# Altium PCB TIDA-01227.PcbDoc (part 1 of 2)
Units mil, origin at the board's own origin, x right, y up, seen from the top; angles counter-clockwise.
Board outline 2300 x 2250 mil, 2 copper layers (Top Layer, Bottom Layer), stack 64.8 mil thick; 107 components, 78 nets, 446 pads, 341 vias.
Unrouted connection lines stored in the file: 1.
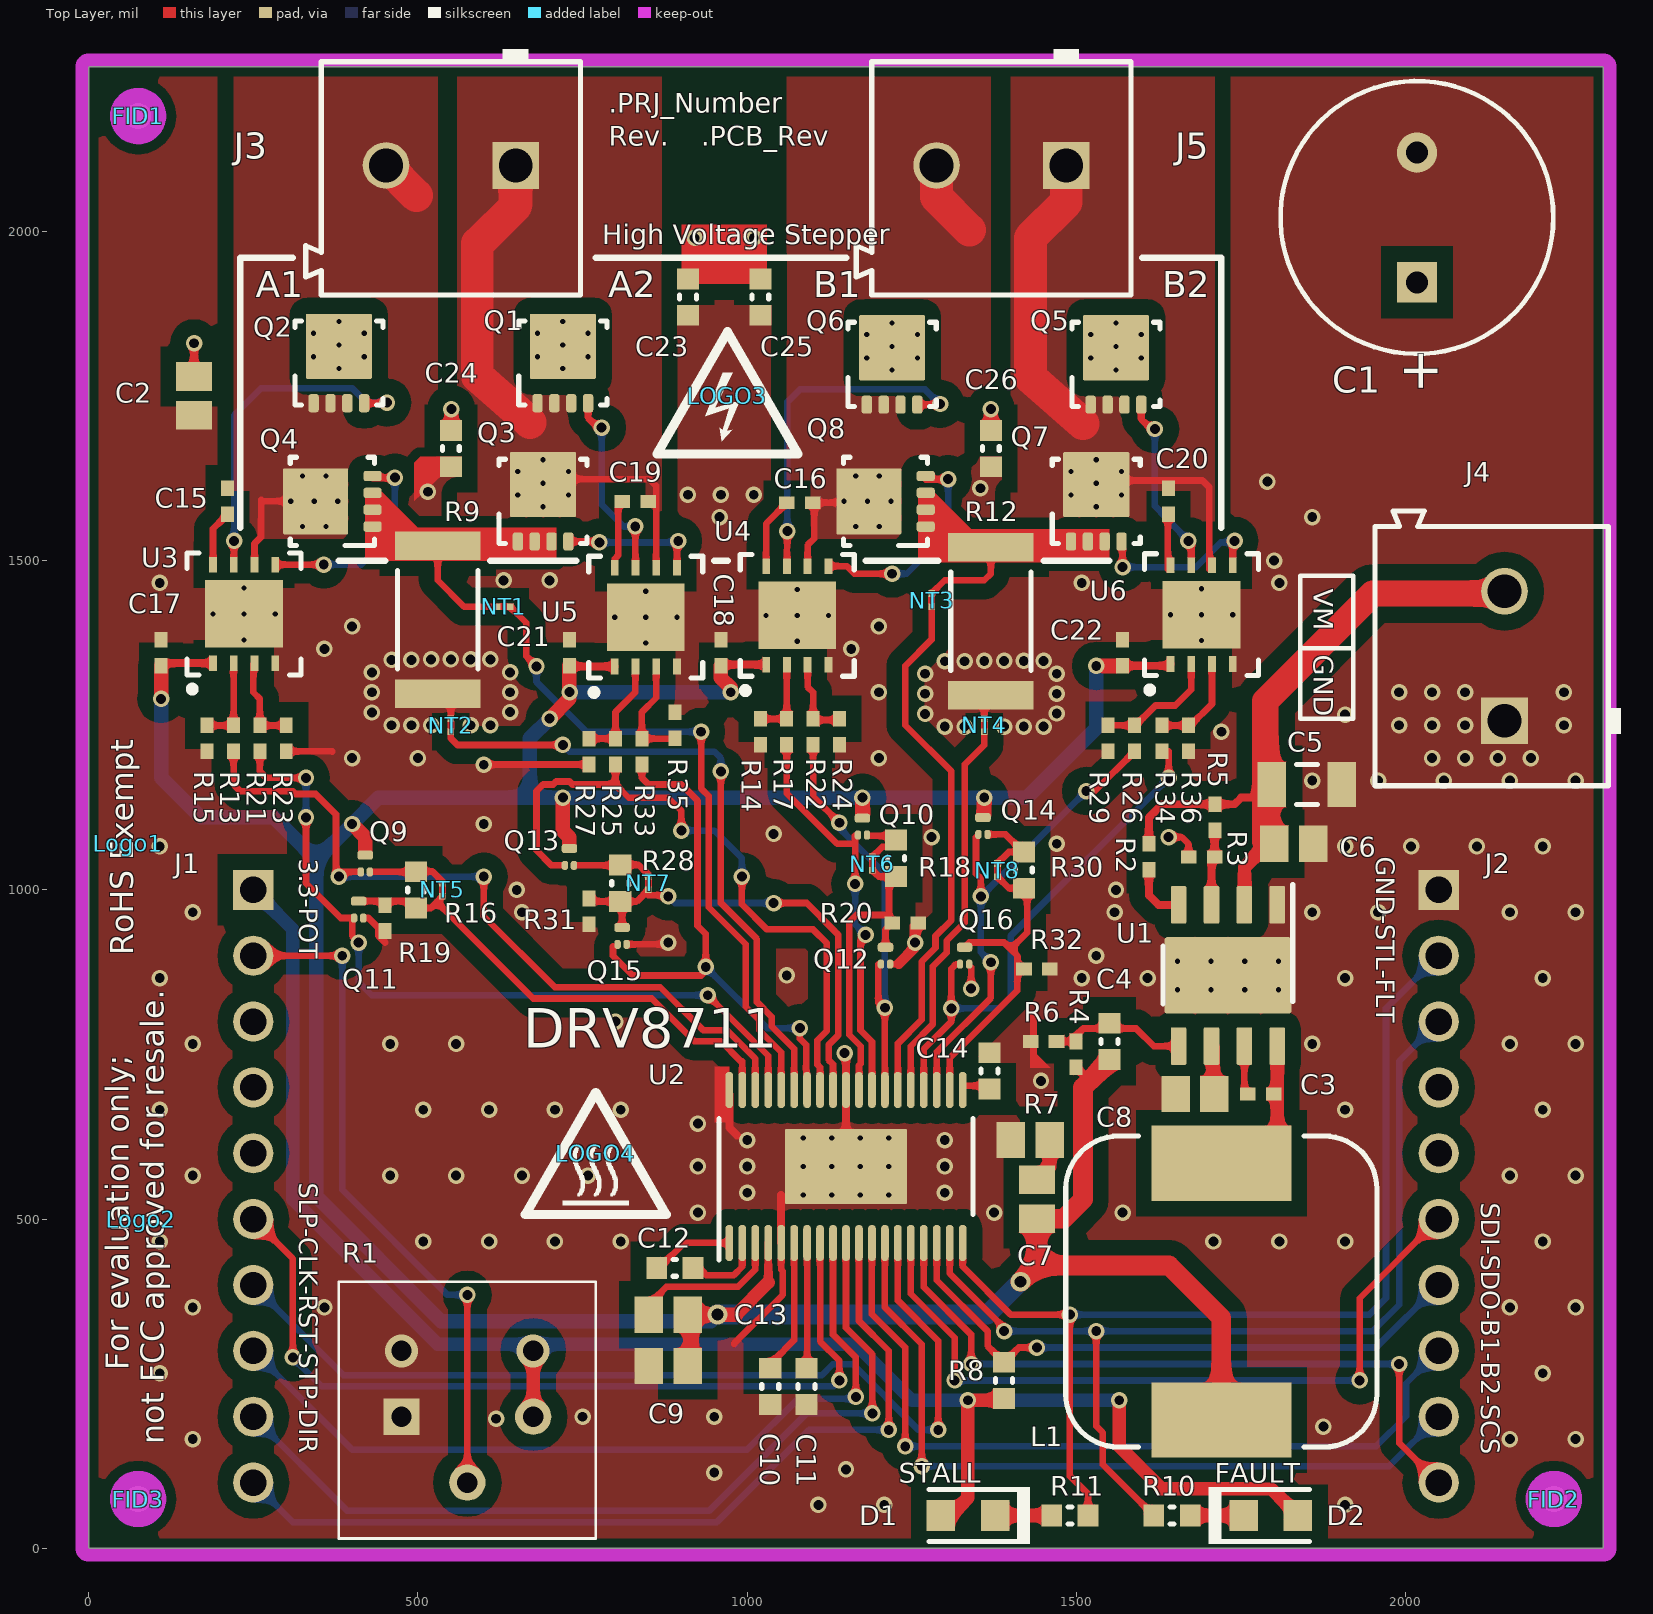
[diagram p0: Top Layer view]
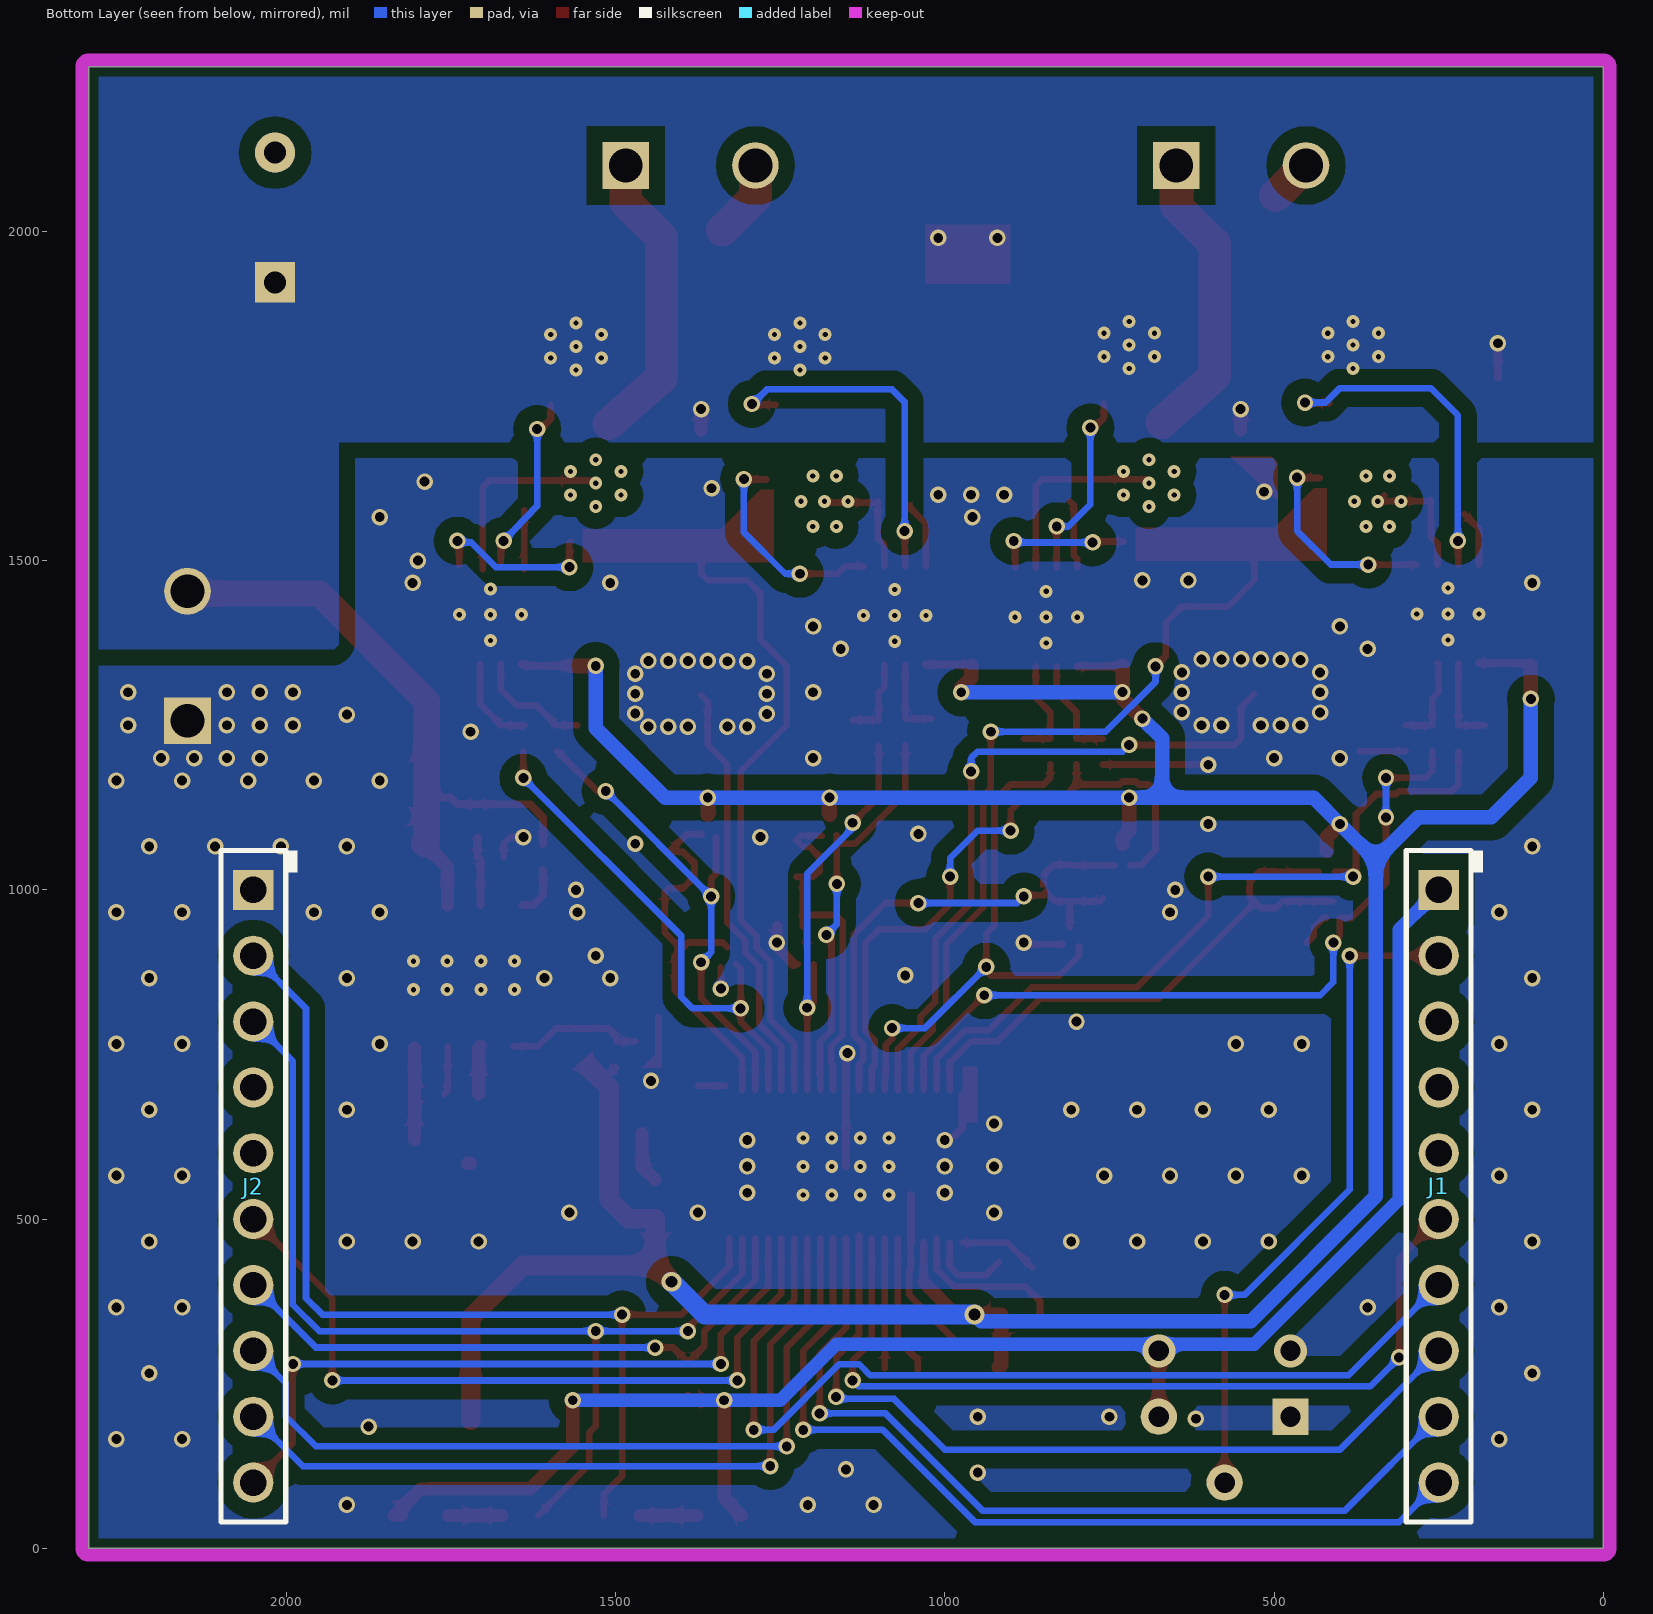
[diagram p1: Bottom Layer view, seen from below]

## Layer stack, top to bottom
Top Solder: solder mask 0.4, Solder Resist, Dk 3.5
Top Layer: signal copper 2.8
Dielectric1: core 59.2, FR-4, Dk 4.8
Bottom Layer: signal copper 2.8
Bottom Solder: solder mask 0.4, Solder Resist, Dk 3.5

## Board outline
0,0 0,2250 2300,2250 2300,0

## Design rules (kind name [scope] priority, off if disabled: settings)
AcuteAngle [All] p1: minimum=4.50000000000000E+0001 checktracksonly=FALSE
AssemblyTestPointUsage [All] p1: valid=2
Clearance Clearance_BoardEdge_MountingHoles [OnCopper and InComponentClass('Mounting Holes') vs IsKeepOut] p1: gap=15
Clearance Clearance_BoardEdge_Poly [OnCopper and InPoly vs IsKeepOut] p2: gap=15
Clearance Clearance_BoardEdge [OnCopper and Not InComponentClass('Logo') and not InComponentClass('FiducialMark') and not InRegion(1000,500,4000,800) and Not IsKeepout vs IsKeepOut] p3: gap=25
Clearance Clearance_Poly [InPolygon] p4: gap=14 except(24: Arc-Poly Track-Poly SMDPad-Poly THPad-Poly Via-Poly Fill-Poly Poly-Poly)
Clearance [All] p5: gap=7 except(3.94: SMDPad-SMDPad)
ComponentClearance ComponentClearance_Logo [InComponentClass(Logo)] p1: gap=10 collisioncheckmode=3 verticalgap=10 showdistances=FALSE
ComponentClearance ComponentClearance_ScrewToNut [(HasFootprint('NY PMS 440 0025 PH')) vs (HasFootprint('Keystone_1902C'))] p2: gap=5 collisioncheckmode=3 verticalgap=10 showdistances=FALSE
ComponentClearance ComponentClearance_MountingHoles [InComponentClass('Mounting Holes')] p3: gap=250 collisioncheckmode=3 verticalgap=100000 showdistances=FALSE
ComponentClearance ComponentClearance_SmallPassives [HasFootprint('0201*') or HasFootprint('0402*') or HasFootprint('0508') or HasFootprint('0603*') or HasFootprint('0612') or HasFootprint('0805*') or HasFootprint('0815*') or HasFootprint('0830*') or HasFootprint('1206*') or HasFootprint('1210*') or HasFootprint('1808*') or HasFootprint('1812*') or HasFootprint('1825*') or HasFootprint('2010*') or HasFootprint('2220*') or HasFootprint('2225*') or HasFootprint('2512*') or HasFootprint('2728*') or HasFootprint('3518*') vs HasFootprint('0201*') or HasFootprint('0402*') or HasFootprint('0508') or HasFootprint('0603*') or HasFootprint('0612') or HasFootprint('0805*') or HasFootprint('0815*') or HasFootprint('0830*') or HasFootprint('1206*') or HasFootprint('1210*') or HasFootprint('1808*') or HasFootprint('1812*') or HasFootprint('1825*') or HasFootprint('2010*') or HasFootprint('2220*') or HasFootprint('2225*') or HasFootprint('2512*') or HasFootprint('2728*') or HasFootprint('3518*')] p4: gap=10 collisioncheckmode=3 verticalgap=10 showdistances=FALSE
ComponentClearance ComponentClearance_THtoSMT [IsThruComponent vs IsSMTComponent] p5: gap=10 collisioncheckmode=3 verticalgap=100000 showdistances=FALSE
ComponentClearance ComponentClearance_THtoTH [IsThruComponent vs IsThruComponent] p6: gap=0 collisioncheckmode=3 verticalgap=0 showdistances=FALSE
ComponentClearance [All] p7: gap=10 collisioncheckmode=3 verticalgap=10 showdistances=FALSE
DiffPairsRouting [All] p1: maxlimit=100 minlimit=10 mostfreqgap=10 toplayer_minwidth=15 toplayer_maxwidth=15 toplayer_prefwidth=15 bottomlayer_minwidth=15 bottomlayer_maxwidth=15 bottomlayer_prefwidth=15 maxuncoupledlength=1000
FabricationTestPointUsage TestPointUsage [All] p1: valid=2 allowmultiple=FALSE
FabricationTestpoint Testpoint [All] p1: side=3 testpointundercomponent=TRUE minsize=40 maxsize=100 preferedsize=60 minholesize=0 maxholesize=40 preferedholesize=32 testpointgrid=1 allowsidetop=TRUE allowsidebottom=TRUE usegrid=TRUE gridtolerance=0.01
FanoutControl Fanout_LCC [IsLCC] p1: bgadir=Out bgaviamode=Centered fanoutstyle=Auto fanoutdirection=Alternating viagrid=1 // Fanout_LCC (Default Rule)
FanoutControl Fanout_BGA [IsBGA] p2: bgadir=Out bgaviamode=Centered fanoutstyle=Auto fanoutdirection=Alternating viagrid=1 // Fanout_BGA (Default Rule)
FanoutControl Fanout_Default [All] p4: bgadir=Out bgaviamode=Centered fanoutstyle=Auto fanoutdirection=Alternating viagrid=1 // Fanout_Default (Default Rule)
FanoutControl Fanout_Small [(CompPinCount < 5)] p5: bgadir=Out bgaviamode=Centered fanoutstyle=Auto fanoutdirection=OutThenIn viagrid=1 // Fanout_Small (Default Rule)
HoleSize [All] p1: absolutevalues=TRUE maxlimit=251 minlimit=7.8 maxpercent=80.000 minpercent=20.000
MinimumAnnularRing [All] p1: minimumring=5
MinimumSolderMaskSliver MinimumSolderMaskSliver_Logo [InComponentClass('Logo') vs InComponentClass('Logo')] p1: minsoldermaskwidth=0.7
MinimumSolderMaskSliver [All] p2: minsoldermaskwidth=0.4
PlaneClearance [All] p1: clearance=15
PlaneConnect [All] p1: planeconnectstyle=Direct reliefexpansion=10 reliefentries=4 reliefconductorwidth=10 reliefairgap=10
PolygonConnect PolygonConnect_1 [IsNamedPolygon('GND_TOP') or IsNamedPolygon('GND_BOT') vs Not (InComponent('U1') or InComponent('J2') or InComponent('J3') or InComponent('J5') or InComponent('C1') or InComponent('R1') or InComponent('R2') or IsStitchingVia or IsVia)] p1: connectstyle=Direct reliefconductorwidth=10 reliefentries=4 polygonreliefangle="90 Angle" airgapwidth=10
PolygonConnect [All] p2: connectstyle=Direct reliefconductorwidth=10 reliefentries=4 polygonreliefangle="90 Angle" airgapwidth=10
RoutingVias [All] p1: holewidth=15 width=25 viastyle="Through Hole" minholewidth=7.8 minwidth=19 maxholewidth=40 maxwidth=65
SMDToCorner [All] p1: distance=15000
SilkToSilkClearance [All] p1: silktosilkclearance=2
SilkToSolderMaskClearance SilkscreenOverComponentPads [All] p1: minsilkscreentomaskgap=1 clearancetoexposedcopper=FALSE
SolderMaskExpansion [All] p1: expansion=3
Width [All] p1: maxlimit=100 minlimit=6 preferedwidth=10 checkconnectedcopper=TRUE
15 further rules are at their usual default settings.

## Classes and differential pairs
component class FiducialMark: FID1 FID2 FID3
component class TIDA-01227_Driver_and_FETs: C9 C10 C11 C12 C13 C14 C23 C24 C25 C26 D1 D2 NT1 NT2 NT3 NT4 Q1 Q2 Q3 Q4 Q5 Q6 Q7 Q8 R8 R9 R10 R11 R12 U2
component class TIDA-01227_Connectors_and_Buck: C1 C2 C3 C4 C5 C6 C7 C8 FID1 FID2 FID3 J1 J2 J3 J4 J5 L1 Logo1 Logo2 LOGO4 R1 R2 R3 R4 R5 R6 R7 U1
component class TIDA-01227_HV_translation: C15 C16 C17 C18 C19 C20 C21 C22 NT5 NT6 NT7 NT8 Q9 Q10 Q11 Q12 Q13 Q14 Q15 Q16 R13 R14 R15 R16 R17 R18 R19 R20 R21 R22 R23 R24 R25 R26 R27 R28 R29 R30 R31 R32 R33 R34 R35 R36 U3 U4 U5 U6

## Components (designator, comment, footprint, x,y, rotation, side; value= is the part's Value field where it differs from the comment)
C1 "ECA-2AHG101" NHG_1000x2000 2017,2021 r90 top
C2 "C0805C104K1RACTU" 0805L 160,1750 r270 top
C3 "885012205031" 0402L 1780,690 r0 top
C4 "06031C562JAT2A" 0603L 1550,770 r90 top
C5 "C3216X7R2A105M160AA" 1206L 1850,1160 r0 top
C6 "C2012X7R2A104K125AA" 0805L 1830,1070 r0 top
C7 "CL21A106KAFN3NE" 0805L 1440,530 r90 top
C8 "GRM21BR71H105KA12L" 0805L 1680,690 r180 top
C9 "GRM21BR71H105KA12L" 0805L 880,277 r180 top
C10 "GRM188R72A104KA35D" 0603L 1035,246 r270 top
C11 "GRM188R71E105KA12D" 0603L 1090,246 r270 top
C12 "GRM188R72A104KA35D" 0603L 890,426 r0 top
C13 "GRM21BR71H105KA12L" 0805L 880,355 r0 top
C14 "C0603X102K5RACTU" 0603L 1368,725 r90 top
C15 "C1005X7R1E104M050BB" 0402L 210.84,1590 r270 top
C16 "C1005X7R1E104M050BB" 0402L 1080,1587.8 r180 top
C17 "C1005X7R1E104M050BB" 0402L 110,1360 r90 top
C18 "C1005X7R1E104M050BB" 0402L 960,1360 r90 top
C19 "C1005X7R1E104M050BB" 0402L 830,1590 r180 top
C20 "C1005X7R1E104M050BB" 0402L 1640,1590 r270 top
C21 "C1005X7R1E104M050BB" 0402L 730,1360 r90 top
C22 "C1005X7R1E104M050BB" 0402L 1570,1360 r90 top
C23 "GRM188R72A104KA35D" 0603L 910,1900 r270 top
C24 "GRM188R72A104KA35D" 0603L 550,1670 r270 top
C25 "GRM188R72A104KA35D" 0603L 1020,1900 r270 top
C26 "GRM188R72A104KA35D" 0603L 1370,1670 r270 top
D1 "150080SS75000" WL-SMCW_RED_0805 1335,50 r180 top
D2 "150080SS75000" WL-SMCW_RED_0805 1795,50 r0 top
FID1 "Fiducial" Fiducial10-20 75,2175 r0 top
FID2 "Fiducial" Fiducial10-20 2225,75 r0 top
FID3 "Fiducial" Fiducial10-20 75,75 r0 top
J1 "61301011821" Wurth_61301011821 250,550 r270 bottom locked
J2 "61301011821" Wurth_61301011821 2050,550 r270 bottom
J3 "691 101 710 002" Wurth_691101710002 550,2100 r180 top
J4 "691 101 710 002" Wurth_691101710002 2150,1355 r90 top
J5 "691 101 710 002" Wurth_691101710002 1386,2100 r180 top
L1 "744770222" WE-PD_1280 1720,390 r270 top
Logo1 "EU RoHS Exempt Logo" EURoHS_Exempt_60mil 60,1070 r90 top
Logo2 "FCC disclaimer" FCC_disclaimer_stacked 80,500 r90 top
LOGO3 "DANGER HIGH VOLTAGE" IEC_HighVoltage_Small 970,1750 r0 top
LOGO4 "CAUTION HOT SURFACE" IEC_HotSurface_Small 770,600 r0 top
NT1 "Net-Tie" Net-Tie_10mil 630,1430 r180 top net-tie
NT2 "Net-Tie" Net-Tie_10mil 550,1250 r90 top net-tie
NT3 "Net-Tie" Net-Tie_10mil 1280,1440 r270 top net-tie
NT4 "Net-Tie" Net-Tie_10mil 1360,1250 r270 top net-tie
NT5 "Net-Tie" Net-Tie_10mil 537.2,1000 r90 top net-tie
NT6 "Net-Tie" Net-Tie_10mil 1190,1040 r90 top net-tie
NT7 "Net-Tie" Net-Tie_10mil 850,1010 r90 top net-tie
NT8 "Net-Tie" Net-Tie_10mil 1380,1030 r90 top net-tie
Q1 "CSD19538Q3A" DNH0008A 720,1800 r90 top
Q2 "CSD19538Q3A" DNH0008A 380,1800 r90 top
Q3 "CSD19538Q3A" DNH0008A 690,1590 r90 top
Q4 "CSD19538Q3A" DNH0008A 370,1590 r180 top
Q5 "CSD19538Q3A" DNH0008A 1560,1797.8 r90 top
Q6 "CSD19538Q3A" DNH0008A 1220,1797.8 r90 top
Q7 "CSD19538Q3A" DNH0008A 1530,1590 r90 top
Q8 "CSD19538Q3A" DNH0008A 1210,1590 r180 top
Q9 "CSD17483F4T" YJC0003A 420,1040 r90 top
Q10 "CSD17483F4T" YJC0003A 1175,1096 r90 top
Q11 "CSD17483F4T" YJC0003A 410,970 r90 top
Q12 "CSD17483F4T" YJC0003A 1210,900 r90 top
Q13 "CSD17483F4T" YJC0003A 730,1050 r90 top
Q14 "CSD17483F4T" YJC0003A 1358,1097 r90 top
Q15 "CSD17483F4T" YJC0003A 810,930 r90 top
Q16 "CSD17483F4T" YJC0003A 1330,900 r90 top
R1 "3386P-1-104LF" BOURNS_3386P 575,210 r0 top locked
R2 "CRCW0402267KFKED" 0402L 1610,1050 r270 top
R3 "CRCW040251K1FKED" 0402L 1710,1110 r90 top
R4 "CRCW04022K67FKED" 0402L 1499,750 r270 top
R5 "CRCW04029K09FKED" 0402L 1690,1050 r0 top
R6 "CRCW0402301RFKED" 0402L 1450,770 r0 top
R7 "ERJ-6RQF2R2V" 0805L 1430,620 r0 top
R8 "CRCW06033K30JNEA" 0603L 1390,255 r270 top
R9 "CRA2512-FZ-R050ELF" 2512L 530,1410 r90 top
R10 "CRCW0603330RJNEA" 0603L 1645,50 r180 top
R11 "CRCW0603330RJNEA" 0603L 1490,50 r180 top
R12 "CRA2512-FZ-R050ELF" 2512L 1370,1407.8 r90 top
R13 "CRCW040218K0FKED" 0402L 220,1230 r270 top
R14 "CRCW040218K0FKED" 0402L 1060,1240 r270 top
R15 "CRCW04023K01FKED" 0402L 180,1230 r90 top
R16 "CRCW0603100RJNEA" 0603L 497.2,1000 r90 top
R17 "CRCW04023K01FKED" 0402L 1020,1240 r90 top
R18 "CRCW0603100RJNEA" 0603L 1226,1048 r90 top
R19 "CRCW0402100KFKED" 0402L 450,957.2 r90 top
R20 "CRCW0402100KFKED" 0402L 1240,950 r180 top
R21 "CRCW040214K0FKED" 0402L 260,1230 r270 top
R22 "CRCW040214K0FKED" 0402L 1100,1240 r270 top
R23 "CRCW04026K98FKED" 0402L 300,1230 r90 top
R24 "CRCW04026K98FKED" 0402L 1140,1240 r90 top
R25 "CRCW040218K0FKED" 0402L 800,1210 r270 top
R26 "CRCW040218K0FKED" 0402L 1588.19,1230 r270 top
R27 "CRCW04023K01FKED" 0402L 760,1210 r90 top
R28 "CRCW0603100RJNEA" 0603L 807.2,1010 r90 top
R29 "CRCW04023K01FKED" 0402L 1548.19,1230 r90 top
R30 "CRCW0603100RJNEA" 0603L 1420,1030 r90 top
R31 "CRCW0402100KFKED" 0402L 760,967.2 r90 top
R32 "CRCW0402100KFKED" 0402L 1440,880 r180 top
R33 "CRCW040214K0FKED" 0402L 840,1210 r270 top
R34 "CRCW040214K0FKED" 0402L 1630,1230 r270 top
R35 "CRCW04026K98FKED" 0402L 890,1250 r270 top
R36 "CRCW04026K98FKED" 0402L 1670,1230 r90 top
U1 "LM5017MRX/NOPB" DDA0008B_N 1730,870 r270 top
U2 "DRV8711DCPR" DCP0038A_N 1150,580 r90 top
U3 "LM5107SD/NOPB" SDC08A 236,1419 r90 top
U4 "LM5107SD/NOPB" SDC08A 1076,1416.8 r90 top
U5 "LM5107SD/NOPB" SDC08A 846,1414 r90 top
U6 "LM5107SD/NOPB" SDC08A 1690,1417.8 r90 top

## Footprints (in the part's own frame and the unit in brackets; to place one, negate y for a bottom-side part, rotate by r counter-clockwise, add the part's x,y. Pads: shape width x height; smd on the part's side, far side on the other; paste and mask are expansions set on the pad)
0402L [mm] "0402 from SM-752 data"
  rect 0.6x0.5 smd: 1(-0.5,0) 2(0.5,0)
  body extent -0.55,-0.3 0.55,0.3, height 0.6
0603L [mm] "0603 from SM-752 data"
  rect 0.8x0.85 smd: 1(-0.7,0) 2(0.7,0)
  silkscreen extent -0.07,-0.33 0.07,0.33, body extent -0.87,-0.47 0.87,0.47, height 1
0805L [mm] "0805 from SM-752 data"
  rect 1.1x1.4 smd: 1(-0.75,0) 2(0.75,0)
  body extent -1.1,-0.72 1.1,0.72, height 1.45
1206L [mm] "1206 from SM-752 data"
  rect 1.1x1.75 smd: 1(-1.35,0) 2(1.35,0)
  silkscreen extent -0.4,-0.77 0.4,0.77, body extent -1.7,-0.9 1.7,0.9, height 1.35
2512L [mm] "Chip Resistor, Body 6.3x3.2mm, IPC High Density"
  rect 1.1x3.3 smd: 1(-2.85,0) 2(2.85,0)
  silkscreen extent -1.9,-1.55 1.9,1.55, body extent -3.22,-1.67 3.22,1.67, height 0.71
BOURNS_3386P [mil] "BOURND"
  rect 55x55 hole 31: 1(-100,-10)
  round 55 hole 31: 2(0,-110) 3(100,-10)
  silkscreen extent -195,-195 195,195, body extent -193,-192 193,193, height 201
DCP0038A_N [mm] "SOP, 38-Leads, Body 9.8x4.5mm, Pitch 0.5mm, Thermal Pad 4.7x2.9mm, IPC Medium Density"
  oval 1.4x0.3 smd: 1(-2.95,4.5) 2(-2.95,4) 3(-2.95,3.5) 4(-2.95,3) 5(-2.95,2.5) 6(-2.95,2) 7(-2.95,1.5) 8(-2.95,1) 9(-2.95,0.5) 10(-2.95,0) 11(-2.95,-0.5) 12(-2.95,-1) 13(-2.95,-1.5) 14(-2.95,-2) 15(-2.95,-2.5) 16(-2.95,-3) 17(-2.95,-3.5) 18(-2.95,-4) 19(-2.95,-4.5) 20(2.95,-4.5) 21(2.95,-4) 22(2.95,-3.5) 23(2.95,-3) 24(2.95,-2.5) 25(2.95,-2) 26(2.95,-1.5) 27(2.95,-1) 28(2.95,-0.5) 29(2.95,0) 30(2.95,0.5) 31(2.95,1) 32(2.95,1.5) 33(2.95,2) 34(2.95,2.5) 35(2.95,3) 36(2.95,3.5) 37(2.95,4) 38(2.95,4.5)
  rrect3% 2.9x4.7 smd: 39(0,0)
  silkscreen extent -3.6,-4.9 1.85,4.9, body extent -3.21,-4.85 3.21,4.85, height 1.2
DDA0008B_N [mm] "SOIC, 8-Leads, Body 4.9x3.9mm, Pitch 1.27mm, Exposed Pad, IPC Medium Density"
  rrect17% 1.45x0.6 smd: 1(-2.725,1.905) 2(-2.725,0.635) 3(-2.725,-0.635) 4(-2.725,-1.905) 5(2.725,-1.905) 6(2.725,-0.635) 7(2.725,0.635) 8(2.725,1.905)
  rrect7% 2.95x4.9 smd paste-1.5 mask-1.5: 9(0,0)
  rrect4% 2.71x3.4 on Top Paste: 9(0,0)
  rrect4% 2.71x3.4 on Top Solder: 9(0,0)
  silkscreen extent -3.5,-2.5 1.1,2.5, body extent -3.01,-2.45 3.01,2.45, height 1.57
DNH0008A [mm] "8 pin VSONP, 0.65 mm pitch"
  rrect50% 0.7x0.4 smd paste-0.05 mask-0.05: 1(-1.55,0.975) 2(-1.55,0.325) 3(-1.55,-0.325) 4(-1.55,-0.975) 5(1.55,-0.975) 6(1.55,-0.325) 7(1.55,0.325) 8(1.55,0.975)
  rrect14% 0.705x1.125 on Top Paste: 9(-0.208,0.662) 9(-0.208,-0.663) 9(0.697,-0.663) 9(0.697,0.662)
  rrect6% 1.775x2.45 on Top Solder: 9(0.327,0)
  rrect4% 2.51x2.55 smd paste-1.5 mask-1.5: 9(0.645,0)
  rect 0.5x0.3 on Top Solder: 9(1.175,-0.975) 9(1.175,-0.325) 9(1.175,0.325) 9(1.175,0.975)
  silkscreen extent -1.62,-1.7 1.62,1.7, body extent -1.65,-1.65 1.65,1.66, height 0.91
EURoHS_Exempt_60mil [mil] "EU RoHS Exempt symbol"
FCC_disclaimer_stacked [mil]
Fiducial10-20 [mm]
  round 1 smd mask+0.5: 1(0,0)
  Top Layer keep-out circle w1.178: c0,0 r0.5
IEC_HighVoltage_Small [mil]
  silkscreen extent -107,-88 107,97
IEC_HotSurface_Small [mil]
  silkscreen extent -107,-93 107,92
Net-Tie_10mil [mil] "10mil net tie, no solder mask opening, no solder paste"
  rect 10x10 smd paste-5 mask-5: 1(-10,0) 2(10,0)
  Top Layer region: -6,5 6,5 6,-5 -6,-5
NHG_1000x2000 [mm] "PANASONIC"
  rect 1.55x1.55 hole 0.85: 1(-2.5,0)
  round 1.55 hole 0.85: 2(2.5,0)
  silkscreen extent -5.26,-5.26 5.26,5.26, body extent -5.21,-5.24 5.24,5.24, height 22.01
SDC08A [mm] "SON, 8-Leads, Body 4x4mm, Pitch 0.8mm, NSC Recommended"
  rect 0.6x0.3 smd paste-0.15 mask+0.051: 1(-1.9,1.2) 2(-1.9,0.4) 3(-1.9,-0.4) 4(-1.9,-1.2) 5(1.9,-1.2) 6(1.9,-0.4) 7(1.9,0.4) 8(1.9,1.2)
  rect 2.6x3 smd paste-1.5 mask+0.051: 9(0,0)
  silkscreen extent -3.02,-2.2 2.35,2.2, body extent -2.05,-2.05 2.05,2.05, height 0.8
WE-PD_1280 [mm] "Wurth Elektronik recommended land pattern"
  rect 2.9x5.4 smd: 1(-4.95,0) 2(4.95,0)
  silkscreen extent -6,-6 6,6, body extent -6,-6 6,6, height 8.01
WL-SMCW_RED_0805 [mm] "SMD, 2-Leads, Body 1.6x0.8mm"
  rect 1.1x1.2 smd: 1(-1.05,0) 2(1.05,0)
  silkscreen extent -2.4,-1.1 1.5,1.1, body extent -1,-0.62 1,0.63, height 0.7
Wurth_61301011821 [mm] "Receptacle, 2.54mm, 10x1, TH"
  rect 1.55x1.55 hole 1.02: 1(-11.43,0)
  round 1.55 hole 1.02: 2(-8.89,0) 3(-6.35,0) 4(-3.81,0) 5(-1.27,0) 6(1.27,0) 7(3.81,0) 8(6.35,0) 9(8.89,0) 10(11.43,0)
  silkscreen extent -12.95,-1.25 12.95,1.7, body extent -12.95,-1.25 12.95,1.25, height 8.5
Wurth_691101710002 [mm] "Terminal Block, 5 mm, 2x1, TH"
  rect 1.8x1.8 hole 1.3: 1(-2.5,0)
  round 1.8 hole 1.3: 2(2.5,0)
  silkscreen extent -5,-4.5 5.6,5, body extent -5.6,-4 5.6,5, height 12.5
YJC0003A [mm] "TI"
  rrect50% 0.25x0.2 on Top Paste: 0(-0.325,-0.2) 0(-0.325,0.2)
  rrect80% 0.35x0.25 smd paste-0.13 mask-0.05: 1(-0.325,0.175) 2(-0.325,-0.175)
  rrect57% 0.35x0.6 smd paste-0.05 mask-0.05: 3(0.325,0)
  body extent -0.5,-0.3 0.5,0.3, height 0.35

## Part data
C1: "CAP, AL, 100 µF, 100 V, +/- 20%, TH"
C2 C6: "CAP, CERM, 0.1 µF, 100 V, +/- 10%, X7R, 0805"
C3: "CAP, CERM, 0.01 µF, 16 V, +/- 10%, X7R, 0402"
C4: "CAP, CERM, 5600 pF, 100 V, +/- 5%, X7R, 0603"
C5: "CAP, CERM, 1 µF, 100 V, +/- 20%, X7R, 1206"
C7: "CAP, CERM, 10 µF, 25 V, +/- 10%, X5R, 0805"
C8 C9 C13: "CAP, CERM, 1 µF, 50 V, +/- 10%, X7R, 0805"
C10 C12 C23 C24 C25 C26: "CAP, CERM, 0.1uF, 100V, +/-10%, X7R, 0603"
C11: "CAP, CERM, 1 µF, 25 V, +/- 10%, X7R, 0603"
C14: "CAP, CERM, 1000 pF, 50 V, +/- 10%, X7R, 0603"
C15 C16 C17 C18 C19 C20 C21 C22: "CAP, CERM, 0.1 µF, 25 V, +/- 20%, X7R, 0402"
D1 D2: "LED, Red, SMD"
FID1 FID2 FID3: "Fiducial mark.  There is nothing to buy or mount."
J1 J2: "Receptacle, 2.54mm, 10x1, Gold, TH"
J3 J4 J5: "Terminal Block, 5 mm, 2x1, Tin, TH"
L1: "Inductor, Shielded Drum Core, Ferrite, 220 µH, 1.3 A, 0.39 ohm, SMD"
Logo1: library part EURoHS_Exempt
Logo2: library part FCC_disclaimer, "FCC_disclaimer"
LOGO3: library part IEC_HighVoltage, "IEC 61010-1 High Voltage Warning"
LOGO4: library part IEC_HotSurface, "IEC 61010-1 Hot Surface Warning"
NT1 NT2 NT3 NT4 NT5 NT6 NT7 NT8: "Single point connection between nets."
Q1 Q2 Q3 Q4 Q5 Q6 Q7 Q8: "MOSFET, N-CH, 100 V, 5 A, VSONP-8"
Q9 Q10 Q11 Q12 Q13 Q14 Q15 Q16: "MOSFET, N/P-CH, 30 V, 1.5 A, 1.0x0.35x0.6mm"
R1: "TRIMMER, 100k ohm, 0.5W, TH"
R2: "RES, 267 k, 1%, 0.063 W, 0402"
R3: "RES, 51.1 k, 1%, 0.063 W, 0402"
R4: "RES, 2.67 k, 1%, 0.063 W, 0402"
R5: "RES, 9.09 k, 1%, 0.063 W, 0402"
R6: "RES, 301, 1%, 0.063 W, 0402"
R7: "RES, 2.20, 1%, 0.125 W, 0805"
R8: "RES, 3.3k ohm, 5%, 0.1W, 0603"
R9 R12: "RES, 0.05 ohm, 1%, 3W, 2512"
R10 R11: "RES, 330 ohm, 5%, 0.1W, 0603"
R13 R14 R25 R26: "RES, 18.0 k, 1%, 0.063 W, AEC-Q200 Grade 0, 0402"
R15 R17 R27 R29: "RES, 3.01 k, 1%, 0.063 W, 0402"
R16 R18 R28 R30: "RES, 100, 5%, 0.1 W, 0603"
R19 R20 R31 R32: "RES, 100 k, 1%, 0.063 W, 0402"
R21 R22 R33 R34: "RES, 14.0 k, 1%, 0.063 W, 0402"
R23 R24 R35 R36: "RES, 6.98 k, 1%, 0.063 W, 0402"
U1: "100V, 600mA Constant On-Time Synchronous Buck Regulator, DDA0008B"
U2: "STEPPER MOTOR CONTROLLER IC, DCP0038A"
U3 U4 U5 U6: "100V / 1.4A Peak Half-Bridge Gate Driver, 8-pin LLP, Pb-Free"

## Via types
v1: diameter 25, hole 15, Top Layer to Bottom Layer, tented both sides, 241 vias
v2: diameter 19.68, hole 7.87, Top Layer to Bottom Layer, 92 vias
v3: diameter 19.68, hole 7.87, Top Layer to Bottom Layer, tented both sides, 4 vias
v4: diameter 50, hole 31, Top Layer to Bottom Layer, tented both sides, 2 vias
v5: diameter 30, hole 18, Top Layer to Bottom Layer, tented both sides, 2 vias

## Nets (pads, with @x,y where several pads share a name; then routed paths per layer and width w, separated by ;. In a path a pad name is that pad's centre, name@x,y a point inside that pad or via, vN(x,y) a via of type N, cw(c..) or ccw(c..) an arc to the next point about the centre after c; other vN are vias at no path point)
3.3V: D1.2 D2.2 J1.1 R1.3 R8.2 | length 2614.8
  Top Layer w20: R1.3@675,200 v4@675,310 ; D1.2@1308.66,50 1335,76.34 v1(1335,225) 1387.56,225 R8.2@1390,227.44 ; v1(1565,225) 1565,155 1629.38,90.62 1782.36,90.62 1782.98,90 1796.34,90 D2.2@1836.34,50 ; D2.2@1825,51.34 D2.2@1826.34,50
  Bottom Layer w20: J1.1@250,1000 310,940 310,530 530,310 1165,310 1250,225 v1(1335,225) v1(1565,225)
  other v4: 675,300
A1HS: Q9.1 R13.2 U2.36 | length 1181.4
  Top Layer w10: R13.2@220,1210.31 220,1160 230,1150 310,1150 314.5,1145.5 344.5,1145.5 375.5,1114.5 375.5,1024.5 v1(380,1020) 387.2,1027.2 408,1027.2 ; v1(600,1020) 600,960 708,852 868,852 933,787 968.96,787 1012.2,743.75 U2.36@1012.2,696.14
  Bottom Layer w10: v1(380,1020) v1(600,1020)
A1HS_DIV: R13.1 R15.2 U3.2 | length 134.6
  Top Layer w10: R15.2@180,1249.69 R13.1@220,1249.68 220,1343.95 U3.2@220.25,1344.2
A1HS_MOT: Q2.4 U3.7 | length 520.9
  Top Layer w10: U3.7@220.25,1493.8 v1(220.76,1530) ; Q2.4@416.39,1738.98 Q2.4@418.39,1738.98 v1@451.98,1738.98
  Bottom Layer w10: v1(220.76,1530) 221,1721 262,1762 399.97,1762 421.97,1740 v1(453,1740)
A1LS: Q11.1 R21.2 U2.35 | length 1174.9
  Top Layer w10: R21.2@260,1210.31 260,1180 270,1170 v1(330,1170) ; v1(330,1110) 330,1010 382.8,957.2 397,957.2 ; Q11.1@399.97,957.2 399.97,930.03 v1(410,920) ; v1(940,840) 1031.89,748.11 U2.35@1031.89,696.14
  Bottom Layer w10: v1(330,1110) v1(330,1170) ; v1(410,920) 410,860 430,840 v1(940,840)
A1LS_DIV: R21.1 R23.2 U3.3 | length 139.4
  Top Layer w10: U3.3@251.75,1344.2 250,1342.45 250,1300 260,1290 R21.1@260,1249.68 R23.2@300,1249.69
A1LS_MOT: Q4.4 U3.5 | length 317
  Top Layer w10: U3.5@283.24,1493.8 v1@356.8,1493.8 ; Q4.4@431.02,1625.39 v1@464.39,1625.39
  Bottom Layer w10: v1(357,1494) 414,1494 465,1545 v1(465,1626)
A2HS: Q13.1 R25.2 U2.31 | length 1006.5
  Top Layer w10: 718,1037.21 702.79,1037.21 680,1060 680,1150 690,1160 705.35,1160 709.85,1164.5 730.15,1164.5 734.65,1160 800,1160 ; R25.2@800,1190.32 800,1160 ; v1(900,1090) 900,1120 880,1140 820,1140 800,1160 ; v1(992,1020) 992,978 1030,940 1100,940 1121,919 1121,786 1106.5,771.5 1106.5,734.81 1110.63,730.68 U2.31@1110.63,696.14 U2.31@1110,696.77
  Bottom Layer w10: v1(900,1090) 950,1090 992,1048 v1(992,1020)
A2HS_DIV: R25.1 R27.2 U5.2 | length 162
  Top Layer w10: R27.2@760,1229.69 R25.1@800,1229.69 800,1270 830.25,1300.25 U5.2@830.25,1339.2
A2HS_MOT: Q1.4 U5.7 | length 294
  Top Layer w10: Q1.4@758.39,1738.98 758.39,1716.61 773,1702 v1(779,1702) ; v1(830,1552) 830.25,1551.75 U5.7@830.25,1488.8
  Bottom Layer w10: v1(779,1702) 779,1585 812,1552 v1(830,1552)
A2LS: Q15.1 R33.2 U2.32 | length 826.8
  Top Layer w10: 796.22,914 796.22,900 826.22,870 930,870 v1@937,877 ; R33.2@840,1190.31 840,1170 850,1160 900,1160 924.5,1135.5 924.5,945.5 937,933 v1(937,883) ; v1(1080,790) 1080,774 1089.5,764.5 1089.5,715.5 1090.94,714.06 U2.32@1090.94,696.14
  Bottom Layer w10: v1(937,883) 1030,790 v1(1080,790)
A2LS_DIV: R33.1 R35.2 U5.3 | length 158.5
  Top Layer w10: U5.3@861.75,1339.2 861.75,1291.75 840,1270 R33.1@840,1229.68 880,1229.69
A2LS_MOT: Q3.4 U5.5 | length 210.7
  Top Layer w10: Q3.4@728.39,1528.98 774.02,1528.98 v1(775.5,1527.5) ; v1@893,1531 893.24,1530.76 U5.5@893.24,1488.8
  Bottom Layer w10: v1(775.5,1527.5) 892.99,1527.5 v1(895.24,1529.76)
AISENN: NT2.1 U2.33 | length 982.4
  Top Layer w10: NT2.1@550,1240 550,1230 560,1220 v1(720,1220) ; v1(960,1180) 960,980 1014.74,925.26 1014.74,829.66 1037,807.4 1037,792.96 1071.26,758.7 U2.33@1071.26,696.14
  Bottom Layer w10: v1(720,1220) 730,1210 950,1210 960,1200 v1(960,1180)
AISENP: NT1.1 U2.34 | length 1008.4
  Top Layer w10: NT1.1@638,1430 NT1.1@640,1430 664.5,1405.5 664.5,1354.82 v1(680,1339.32) ; v1(930,1240) 930,1154.04 941.5,1142.54 941.5,973.5 997.74,917.26 997.74,822.62 1018.34,802.02 1018.34,786.66 1051.57,753.43 U2.34@1051.57,696.14
  Bottom Layer w10: v1(680,1339.32) 680,1315.74 755.74,1240 v1(930,1240)
AOUT1: NT5.1 Q11.3 R16.1 R19.2 U2.37 | length 746.2
  Top Layer w10: Q11.3@410,982.8 486.85,982.8 R16.1@497.2,972.44 519.65,972.44 528.6,981.4 ; NT5.1@537.2,990 528.6,981.4 ; U2.37@992.52,696.14 992.52,739.4 990.6,739.4 960,770 920,770 855,835 675,835 528.6,981.4
AOUT1_MOT: C15.1 J3.2 Q2.1 Q2.2 Q2.3 Q4.5 Q4.6 Q4.7 Q4.8 Q4.9@344.61,1590 U3.6 | length 255.4
  Top Layer w10: U3.6@251.75,1493.8 251.75,1525.75 261.68,1535.68 262,1592.28 ; 262,1590.32 Q4.9@332.92,1590.32 ; Q4.9@332.61,1599 Q4.9@344.61,1587
  Top Layer w50: J3.2@451.57,2100 497.5,2054.07
  other v2: 324.72,1551.61 360.35,1551.61 306.91,1590 342.54,1590 378.17,1590 324.72,1628.39 360.35,1628.39
AOUT2: NT7.1 Q15.3 R28.1 R31.2 U2.30 | length 680.4
  Top Layer w10: R31.2@760,986.89 764.44,982.44 R28.1@807.2,982.44 810,979.65 Q15.3@810,942.8 ; R28.1@810,982.44 832.44,982.44 NT7.1@846,996 ; 850,992 v1@872,992 ; v1(1040,980) 1090.35,980 1132,938.35 1132,938 1138,932 1138,778.96 1123.5,764.46 1123.5,741.85 1130.31,735.04 U2.30@1130.31,696.14
  Bottom Layer w10: v1(880,990) 890,980 v1(1040,980)
AOUT2_MOT: C19.1 J3.1 Q1.1 Q1.2 Q1.3 Q3.5 Q3.6 Q3.7 Q3.8 Q3.9@690,1615.39 U5.6 | length 747.7
  Top Layer w10: Q3.9@694.29,1623.8 825,1623.8 851.24,1623.76 861.75,1613.25 U5.6@861.75,1488.8
  Top Layer w50: J3.1@648.43,2100 648.43,2038.43 591.57,1981.57 590,1981.57 590,1780 670,1710
  other v2: 690,1581.83 651.61,1599.65 728.39,1599.65 690,1617.46 651.61,1635.28 728.39,1635.28 690,1653.09
B1HS: Q10.1 R14.2 U2.27 | length 606.3
  Top Layer w10: R14.2@1060,1220.31 1060,1146.41 1136.41,1070 1163.65,1070 ; v1(1163.9,1008.96) 1163.9,1069.75 1163.65,1070 ; Q10.1@1164.97,1083.2 1163.65,1081.88 1163.65,1070 ; v1@1176.04,922.96 1172,922.96 1172,786.96 1189.5,769.46 1189.5,718.46 1189.37,718.33 U2.27@1189.37,696.14
  Bottom Layer w10: v1(1163.9,1008.96) 1163.9,947.47 v1(1179.88,931.5)
B1HS_DIV: R14.1 R17.2 U4.2 | length 122.4
  Top Layer w10: R17.2@1020,1259.69 R14.1@1060,1259.68 1060,1341.74 U4.2@1060.25,1341.99
B1HS_MOT: Q6.4 U4.7 | length 534.1
  Top Layer w10: U4.7@1060.25,1491.6 v1(1061,1544.8) ; Q6.4@1256.39,1736.77 Q6.4@1258.39,1736.77 v1@1291.98,1736.77
  Bottom Layer w10: v1(1061,1544.8) 1061,1741 1080,1760 1270,1760 1292.2,1737.8 v1(1293,1737.8)
B1LS: Q12.1 R22.2 U2.26 | length 645
  Top Layer w10: R22.2@1100,1218.5 1100,1141.82 v1(1140,1101.82) ; v1@1199,828.26 Q12.1@1199,887.2 ; v1@1201.74,828.26 v1(1209.06,820.94) U2.26@1209.06,696.14
  Bottom Layer w10: v1@1140,1110 v1(1140,1101.82) 1140,1093.65 1209.06,1024.59 v1(1209.06,820.94)
B1LS_DIV: R22.1 R24.2 U4.3 | length 127.5
  Top Layer w10: U4.3@1091.75,1341.99 1091.75,1308.25 1100,1300 1100,1257.87 R24.2@1140,1257.87
B1LS_MOT: Q8.4 U4.5 | length 326.9
  Top Layer w10: U4.5@1123.24,1491.6 1151.08,1491.6 1162.68,1480 v1(1220,1480) ; Q8.4@1271.02,1623.18 v1@1304.39,1623.18
  Bottom Layer w10: v1(1220,1480) 1242.2,1480 1305,1542.8 v1(1305,1623.8)
B2HS: Q14.1 R26.2 U2.22 | length 757.8
  Top Layer w10: U2.22@1287.8,696.14 1287.8,753.8 1370,836 v1(1370,890) ; Q14.1@1347.37,1080 1347.37,1024.59 1354.87,1017.09 v1(1354.87,990) 1351.74,993.13 v1@1351.11,994.5 ; v1(1514.87,1150) 1527.87,1150 R26.2@1588.19,1210.31
  Bottom Layer w10: v1(1370,890) 1354.87,905.13 v1(1354.87,990) v1(1514.87,1150)
B2HS_DIV: R26.1 R29.2 U6.2 | length 177.4
  Top Layer w10: 1558.19,1249.68 1589.68,1249.68 1620,1280 1650,1280 1674.25,1304.25 U6.2@1674.25,1342.99
B2HS_MOT: Q5.4 U6.7 | length 278.5
  Top Layer w10: Q5.4@1598.39,1736.77 1598.39,1714.41 1613,1699.8 v1(1619,1699.8) ; U6.7@1674.25,1492.6 v1@1674.25,1525.54
  Top Layer w12: v1(1670,1529.8) v1@1674.25,1525.54
  Bottom Layer w10: v1(1619,1699.8) 1619,1582.8 v1(1670,1529.8)
B2LS: Q16.1 R34.2 U2.23 | length 781.3
  Top Layer w10: U2.23@1268.11,696.14 1268.11,758.15 1310,800.04 v1(1310,820) 1309.8,820.2 1309.8,879.8 1317.2,887.2 ; v1(1640,1170) 1640,1210.31
  Bottom Layer w10: v1(1310,820) 1383,820 1400,837 1400,930 v1(1640,1170)
B2LS_DIV: R34.1 R36.2 U6.3 | length 141.8
  Top Layer w10: R34.1@1638.21,1249.69 1673.21,1249.69 1674.21,1250.68 1705.75,1282.22 U6.3@1705.75,1342.99
B2LS_MOT: Q7.4 U6.5 | length 262.5
  Top Layer w10: Q7.4@1568.39,1528.98 1570,1527.36 v1(1570,1490) ; v1@1733,1528.8 v1@1733.24,1528.55 ; U6.5@1737.24,1492.6 1737.24,1527.24 v1(1740,1530)
  Bottom Layer w10: v1(1570,1490) 1681.5,1490 1719.05,1527.55 1735.24,1527.55 v1@1732.99,1525.3
BEMF: C14.1 U2.20 | length 41.5
  Top Layer w10: 1333.46,702.44 C14.1@1375,702.44
BIN1: J2.8 U2.12 | length 1236.1
  Top Layer w10: U2.12@1189.37,470.75 1189.37,355.63 1240,305 v1(1240,155)
  Bottom Layer w10: v1(1240,155) 1955,155 2000.79,200.79 2000.79,250.79 J2.8@2050,300
BIN2: J2.9 U2.13 | length 1185
  Top Layer w10: U2.13@1209.06,470.75 1209.06,365.94 1265,310 v1(1265,125)
  Bottom Layer w10: v1(1265,125) 1975,125 J2.9@2050,200
BISENN: NT4.2 U2.24 | length 590.1
  Top Layer w10: U2.24@1248.43,696.14 1248.43,762.51 1282,796.08 1282,883.96 1299.35,901.31 1302.96,904.92 1302.96,922.88 1330.37,950.29 1330.37,1190.37 1360,1220 NT4.2@1360,1240
BISENP: NT3.2 U2.25 | length 813.1
  Top Layer w10: U2.25@1228.74,696.14 1228.74,766.86 1265,803.12 1265,891 1285.96,911.96 1285.96,929.93 1310,953.96 1310,1180 1240,1250 1240,1340 1280,1380 NT3.2@1280,1430
BOUT1: NT6.1 Q12.3 R18.1 R20.2 U2.28 | length 470.7
  Top Layer w10: U2.28@1169.68,696.14 1169.68,733.23 1172.5,736.04 1172.5,762.42 1155,779.92 1155,951.1 1165.71,961.81 1213.5,961.81 ; NT6.1@1190,1030 1200,1020 R18.1@1225.56,1020 ; Q12.3@1210,912.8 1210,939.69 1215.31,945 R18.1@1215.31,1015.31
BOUT1_MOT: C16.1 J5.2 Q6.1 Q6.2 Q6.3 Q8.5 Q8.6 Q8.7 Q8.8 Q8.9@1184.61,1590 U4.6 | length 292.3
  Top Layer w10: U4.6@1091.75,1491.6 1091.75,1523.54 1101.68,1533.48 C16.1@1102,1590.08 ; C16.1@1102,1588.11 Q8.9@1172.92,1588.11
  Top Layer w50: J5.2@1287.57,2100 1287.57,2051.8 1337.5,2001.87
  other v2: 1164.72,1551.61 1200.35,1551.61 1146.91,1590 1182.54,1590 1218.17,1590 1164.72,1628.39 1200.35,1628.39
BOUT2: NT8.1 Q16.3 R30.1 R32.2 U2.21 | length 482.5
  Top Layer w10: U2.21@1307.48,696.14 1307.48,744.48 1410,847 1410,900 1400,910 ; Q16.3@1330,912.8 1337.2,920 1390,920 1400,910 ; NT8.1@1380,1020 1397.56,1002.44 R30.1@1420,1002.44 ; R30.1@1425,997.32 1425,935 1400,910
BOUT2_MOT: C20.1 J5.1 Q5.1 Q5.2 Q5.3 Q7.5 Q7.6 Q7.7 Q7.8 Q7.9@1530,1615.39 U6.6 | length 747.3
  Top Layer w10: Q7.9@1534.29,1621.59 1665,1621.59 1691.24,1621.55 1701.75,1611.05 U6.6@1701.75,1486.6
  Top Layer w50: J5.1@1484.43,2100 1484.43,2044.43 1430,1990 1430,1777.8 1510,1707.8
  other v2: 1530,1581.83 1491.61,1599.65 1568.39,1599.65 1530,1617.46 1491.61,1635.28 1568.39,1635.28 1530,1653.09
CP1: C12.1 U2.1 | length 122.1
  Top Layer w10: C12.1@866.44,426 904.3,463.86 U2.1@972.83,463.86
CP2: C12.2 U2.2 | length 124.7
  Top Layer w10: C12.2@917.56,435 937.56,415 979.85,415 992.52,427.67 U2.2@992.52,463.86
DIR/AIN2: J1.10 U2.11 | length 1357.4
  Top Layer w10: U2.11@1169.68,470.75 1169.68,345.32 1215,300 v1(1215,180)
  Bottom Layer w10: J1.10@250,100 310,40 953.98,40 1093.98,180 v1(1215,180)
